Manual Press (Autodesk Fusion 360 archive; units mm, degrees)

design "Manual Press" references "Handle", "Gear", "Rod", "Press Top", "Shaft", "Rack", "Base Plate", "Cover Plate", "Shaft Cap"
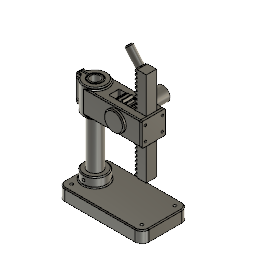
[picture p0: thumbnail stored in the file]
component_insert "Component Insert1"
ground "Ground1"
component_insert "Component Insert2"
joint "Assemble1" OffsetX 0 OffsetY 0 OffsetZ 0 AngleZ 0 OffsetX 0 OffsetY 0 OffsetZ 0 AngleZ 0 alignAngle 0 alignOffsetX 0 alignOffsetY 0 alignOffsetZ 0
component_insert "Component Insert4"
joint "Assemble2" OffsetX 0 OffsetY 0 OffsetZ 0 AngleZ 0 OffsetX 0 OffsetY 0 OffsetZ 0 AngleZ 0 alignAngle 0 alignOffsetX 0 alignOffsetY 0 alignOffsetZ 0
component_insert "Component Insert5"
joint "Assemble3" OffsetX 0 OffsetY 0 OffsetZ 0 AngleZ 0 OffsetX 0 OffsetY 0 OffsetZ 0 AngleZ 0 alignAngle 0 alignOffsetX 0 alignOffsetY 0 alignOffsetZ 0
component_insert "Component Insert6"
joint "Assemble4" OffsetX 0 OffsetY 0 OffsetZ 0 AngleZ 0 OffsetX 0 OffsetY 0 OffsetZ 0 AngleZ 0 alignAngle 0 alignOffsetX 0 alignOffsetY 0 alignOffsetZ 0
component_insert "Component Insert7"
joint "Assemble5" OffsetX 0 OffsetY 0 OffsetZ 0 AngleZ 0 OffsetX 0 OffsetY 0 OffsetZ 0 AngleZ 0 alignAngle 0 alignOffsetX 0 alignOffsetY 0 alignOffsetZ 0
component_insert "Component Insert8"
joint "Assemble6" OffsetX 0 OffsetY 0 OffsetZ 0 AngleZ 0 OffsetX 0 OffsetY 0 OffsetZ 0 AngleZ 0 alignAngle 0 alignOffsetX 0 alignOffsetY 0 alignOffsetZ 0 DistanceMinimum -55 DistanceMaximum 60
component_insert "Component Insert9"
position "Position1"
joint "Assemble7" OffsetX 0 OffsetY 0 OffsetZ 0 AngleZ 0 OffsetX 0 OffsetY 0 OffsetZ 0 AngleZ 0 alignAngle 0 alignOffsetX 0 alignOffsetY 0 alignOffsetZ 0
component_insert "Component Insert10"
joint "Assemble8" OffsetX 0 OffsetY 0 OffsetZ 0 AngleZ 0 OffsetX 0 OffsetY 0 OffsetZ 0 AngleZ 0 alignAngle 0 alignOffsetX 0 alignOffsetY 0 alignOffsetZ 0
position "Position2"
motion_link "MotionLink1" Value1 360 Value2 160

design "Base Plate"
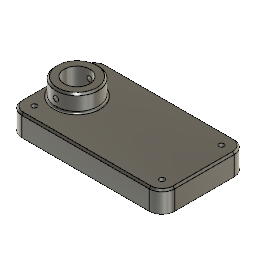
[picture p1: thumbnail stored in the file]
sketch "Sketch1" plane through (0, 0, 0) normal (0, 0, 1) x axis (1, 0, 0)
  line L1 (-90, 50) -> (90, 50)
  line L2 (-90, -50) -> (-90, 50)
  line L3 (90, -50) -> (-90, -50)
  line L4 (90, 50) -> (90, -50)
  line L5 (-90, -50) -> (90, 50)
  line L6 (90, -50) -> (-90, 50)
  point P6 (0, 0)
  point P1 (0, 0)
  point P4 (-90, -50)
  point P5 (90, -50)
  point P3 (-90, 50)
  horizontal L1
  perpendicular L1 L2
  parallel L1 L3
  parallel L2 L4
  coincident L5 P6
  coincident L6 P6
  coincident P1 P6
  dimension "d1" distance P4 P5 = 180
  dimension "d2" distance P3 P4 = 100
extrude "Extrude1" new body sketch "Sketch1" profile of L1 L2 L3 L4 along normal blind 25
fillet "Fillet1" radius 15
sketch "Sketch2" plane through (0, 0, 25) normal (0, 0, 1) x axis (-1, 0, 0)
  line L1 (90, 35) -> (90, -35)
  line L2 (-75, 50) -> (75, 50)
  line L3 (-90, -35) -> (-90, 35)
  line L4 (75, -50) -> (-75, -50)
  arc A1 centre (75, -35) radius 15 clockwise from (90, -35) to (75, -50)
  arc A2 centre (75, 35) radius 15 clockwise from (75, 50) to (90, 35)
  arc A3 centre (-75, 35) radius 15 clockwise from (-90, 35) to (-75, 50)
  arc A4 centre (-75, -35) radius 15 clockwise from (-75, -50) to (-90, -35)
  circle C1 centre (60, 0) radius 15
  point P14 (60, 0)
  dimension "d6" distance L1 P14 = 30
  dimension "d7" distance L4 P14 = 50
  dimension "d8" diameter C1 = 30
extrude "Extrude2" cut sketch "Sketch2" profile of C1 no distance stored
sketch "Sketch3" plane through (0, 0, 25) normal (0, 0, 1) x axis (-1, 0, 0)
  line L1 (90, 35) -> (90, -35)
  line L2 (-75, 50) -> (75, 50)
  line L3 (-90, -35) -> (-90, 35)
  line L4 (75, -50) -> (-75, -50)
  circle C1 centre (60, 0) radius 15
  arc A1 centre (75, -35) radius 15 clockwise from (90, -35) to (75, -50)
  arc A2 centre (75, 35) radius 15 clockwise from (75, 50) to (90, 35)
  arc A3 centre (-75, 35) radius 15 clockwise from (-90, 35) to (-75, 50)
  arc A4 centre (-75, -35) radius 15 clockwise from (-75, -50) to (-90, -35)
  circle C2 centre (60, 0) radius 15
  circle C3 centre (60, 0) radius 25
  concentric C1 C2
  concentric C1 C3
  equal C1 C2
  dimension "d10" diameter C3 = 50
extrude "Extrude3" add sketch "Sketch3" profile of C1 C2 C3 along normal blind 20
chamfer "Chamfer1" distance 2 rotateAngle 45
fillet "Fillet2" radius 2
sketch "Sketch4" plane through (0, 0, 0) normal (0, 1, 0) x axis (1, 0, 0)
  line L1 (-35, -45) -> (-85, -45)
  line L2 (75, 0) -> (-75, 0)
  circle C1 centre (-60, -35) radius 3
  point P2 (-60, -35)
  point P3 (-85, -45)
  dimension "d16" diameter C1 = 6
  dimension "d18" distance P2 P3 = 25
  dimension "d28" distance P2 L2 = 35
extrude "Extrude4" cut sketch "Sketch4" profile of C1 no distance stored
chamfer "Chamfer2" distance 2 rotateAngle 45
sketch "Sketch5" plane through (0, 0, 25) normal (0, 0, 1) x axis (-1, 0, 0)
  line L1 (75, -48) -> (-75, -48)
  line L2 (88, 35) -> (88, -35)
  line L3 (-75, 48) -> (75, 48)
  line L4 (-88, -35) -> (-88, 35)
  arc A1 centre (-75, -35) radius 13 clockwise from (-75, -48) to (-88, -35)
  arc A2 centre (75, -35) radius 13 clockwise from (88, -35) to (75, -48)
  arc A3 centre (75, 35) radius 13 clockwise from (75, 48) to (88, 35)
  arc A4 centre (-75, 35) radius 13 clockwise from (-88, 35) to (-75, 48)
  circle C1 centre (60, 0) radius 27
  circle C2 centre (75, 35) radius 3
  concentric A3 C2
  dimension "d22" diameter C2 = 6
extrude "Extrude5" cut sketch "Sketch5" profile of C2 no distance stored
rectangular_pattern "R-Pattern1" uSpaceDistance 150 vSpaceDistance 70

design "Shaft Cap"
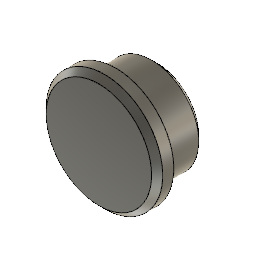
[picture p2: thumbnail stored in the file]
sketch "Sketch1" plane through (0, 0, 0) normal (0, 1, 0) x axis (1, 0, 0)
  circle C1 centre (0, 0) radius 17
  circle C2 centre (0, 0) radius 10
  point P1 (0, 0)
  point P2 (0, 0)
  point P3 (0, 0)
  coincident P1 P2
  coincident P1 P3
  dimension "d1" diameter C1 = 34
  dimension "d5" diameter C2 = 20
extrude "Extrude1" new body sketch "Sketch1" along normal blind 15
sketch "Sketch3" plane through (0, 0, 0) normal (0, -1, 0) x axis (1, 0, 0)
  circle C1 centre (0, 0) radius 10
  circle C2 centre (0, 0) radius 17
  circle C3 centre (0, 0) radius 21
  point P1 (0, 0)
  point P3 (0, 0)
  coincident P1 P3
  dimension "d6" diameter C3 = 42
extrude "Extrude2" add sketch "Sketch3" along normal blind 6
chamfer "Chamfer1" distance 2 rotateAngle 45
chamfer "Chamfer2" distance 2 rotateAngle 45

design "Rack"
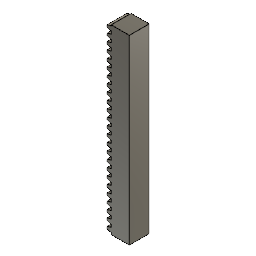
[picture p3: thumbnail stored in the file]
sketch "Sketch1" plane through (0, 0, 0) normal (0, 1, 0) x axis (1, 0, 0)
  line L1 (-10, -100) -> (10, -100)
  line L2 (-10, 100) -> (-10, -100)
  line L3 (10, 100) -> (-10, 100)
  line L4 (10, -100) -> (10, 100)
  line L5 (-10, 100) -> (10, -100)
  line L6 (10, 100) -> (-10, -100)
  point P6 (0, 0)
  point P1 (0, 0)
  point P2 (10, -100)
  point P3 (-10, -100)
  point P5 (10, 100)
  horizontal L1
  perpendicular L1 L2
  parallel L1 L3
  parallel L2 L4
  coincident L5 P6
  coincident L6 P6
  coincident P1 P6
  dimension "d1" distance P2 P3 = 20
  dimension "d2" distance P2 P5 = 200
extrude "Extrude1" new body sketch "Sketch1" profile of L1 L2 L3 L4 distance 22
sketch "Sketch2" plane through (0, -11, 0) normal (0, -1, 0) x axis (1, 0, 0)
  line L1 (10, -100) -> (-10, -100)
  line L2 (10, 100) -> (10, -100)
  line L3 (-10, 100) -> (10, 100)
  line L4 (-10, -100) -> (-10, 100)
  line L5 (-15, -96.5) -> (-15, -94.5)
  line L6 (-7.2745, -95.5) -> (-15, -95.5)
  arc A1 centre (-8.2555, -83.1018) radius 15 clockwise from (-10, -98) to (-15, -96.5)
  arc A2 centre (-8.2555, -107.8982) radius 15 clockwise from (-15, -94.5) to (-10, -93)
  point P8 (-10, -98)
  point P10 (-10, -93)
  point P12 (-15, -95.5)
  point P6 (-15, -94.5)
  point P7 (-15, -96.5)
  parallel L4 L5
  coincident L4 P8
  coincident L4 P10
  equal A1 A2
  midpoint L5 P12
  perpendicular L5 L6
  symmetric P8 P10 L6
  dimension "d5" distance L4 L5 = 5
  dimension "d6" distance P6 P7 = 2
  dimension "d7" radius A2 = 15
  dimension "d8" distance L1 P8 = 2
  dimension "d9" distance P8 P10 = 5
extrude "Extrude2" add sketch "Sketch2" profile of L4 L5 A1 A2 to an object
rectangular_pattern "R-Pattern1" countU 25 uSpaceDistance -8 vSpaceDistance 0

design "Handle"
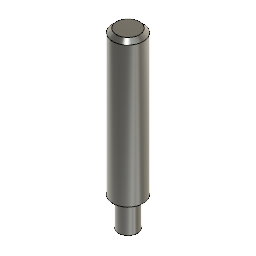
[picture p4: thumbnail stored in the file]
sketch "Sketch1" plane through (0, 0, 0) normal (0, 0, 1) x axis (1, 0, 0)
  circle C1 centre (0, 0) radius 8
  point P1 (0, 0)
  point P2 (0, 0)
  coincident P1 P2
  dimension "d1" diameter C1 = 16
extrude "Extrude1" new body sketch "Sketch1" along normal blind 75
sketch "Sketch2" plane through (0, 0, 0) normal (0, 0, -1) x axis (1, 0, 0)
  circle C1 centre (0, 0) radius 8
  circle C2 centre (0, 0) radius 5
  point P1 (0, 0)
  point P3 (0, 0)
  coincident P1 P3
  dimension "d4" diameter C2 = 10
extrude "Extrude2" add sketch "Sketch2" profile of C2 along normal blind 15
chamfer "Chamfer1" distance 2 rotateAngle 45

design "Cover Plate"
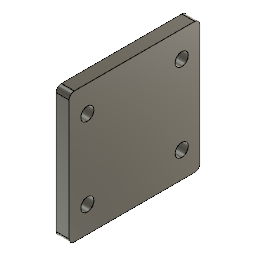
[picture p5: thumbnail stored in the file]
sketch "Sketch1" plane through (0, 0, 0) normal (1, 0, 0) x axis (0, 1, 0)
  line L1 (-25, 25) -> (25, 25)
  line L2 (-25, -25) -> (-25, 25)
  line L3 (25, -25) -> (-25, -25)
  line L4 (25, 25) -> (25, -25)
  line L5 (-25, -25) -> (25, 25)
  line L6 (25, -25) -> (-25, 25)
  point P6 (0, 0)
  point P1 (0, 0)
  point P3 (-25, 25)
  point P4 (-25, -25)
  point P5 (25, -25)
  horizontal L1
  perpendicular L1 L2
  parallel L1 L3
  parallel L2 L4
  coincident L5 P6
  coincident L6 P6
  coincident P1 P6
  dimension "d1" distance P3 P4 = 50
  dimension "d2" distance P4 P5 = 50
extrude "Extrude1" new body sketch "Sketch1" profile of L1 L2 L3 L4 along normal blind 5
fillet "Fillet1" radius 2
hole "Hole1" HoleDepth 5 HoleDiameter 5 TipAngle 118 RefDim1 10 RefDim2 7
rectangular_pattern "R-Pattern1" uSpaceDistance 36 vSpaceDistance 30

design "Shaft"
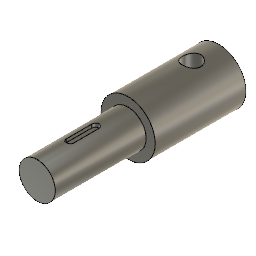
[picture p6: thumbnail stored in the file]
sketch "Sketch1" plane through (0, 0, 0) normal (0, 1, 0) x axis (1, 0, 0)
  circle C1 centre (0, 0) radius 10
  point P1 (0, 0)
  point P2 (0, 0)
  coincident P1 P2
  dimension "d1" diameter C1 = 20
  dimension "d21" distance = 15
extrude "Extrude1" new body sketch "Sketch1" along normal blind 50
sketch "Sketch2" plane through (0, 50, 0) normal (0, 1, 0) x axis (-1, 0, 0)
  circle C1 centre (0, 0) radius 10
  circle C2 centre (0, 0) radius 15
  point P1 (0, 0)
  point P3 (0, 0)
  coincident P1 P3
  dimension "d4" diameter C2 = 30
extrude "Extrude2" add sketch "Sketch2" along normal blind 50
work_plane "WorkPlane1" AlongDistance 10
sketch "Sketch3" plane through (0, 0, 10) normal (0, 0, 1) x axis (1, 0, 0)
  line L1 (2, 32) -> (2, 18)
  line L2 (-2, 18) -> (-2, 32)
  line L3 (0, 32) -> (0, 18)
  line L4 (-15, 50) -> (15, 50)
  arc A1 centre (0, 32) radius 2 clockwise from (-2, 32) to (2, 32)
  arc A2 centre (0, 18) radius 2 clockwise from (2, 18) to (-2, 18)
  point P8 (0, 25)
  point P1 (0, 0)
  point P6 (0, 18)
  point P7 (0, 32)
  tangent L1 A1
  tangent A1 L2
  parallel L1 L2
  tangent L2 A2
  tangent L1 A2
  vertical L3
  midpoint L3 P8
  vertical P1 P6
  dimension "d12" radius A2 = 2
  dimension "d13" distance P6 P7 = 14
  dimension "d14" distance P8 L4 = 25
extrude "Extrude3" cut sketch "Sketch3" profile of L1 A1 L2 A2 against normal blind 2
work_plane "WorkPlane2" AlongDistance 15
sketch "Sketch4" plane through (0, 0, 15) normal (0, 0, 1) x axis (1, 0, 0)
  line L1 (-15, 100) -> (15, 100)
  circle C1 centre (0, 85) radius 5
  point P1 (0, 0)
  point P2 (0, 85)
  vertical P1 P2
  dimension "d20" diameter C1 = 10
  dimension "d24" distance P2 L1 = 15
extrude "Extrude4" cut sketch "Sketch4" profile of C1 against normal blind 15

design "Gear"
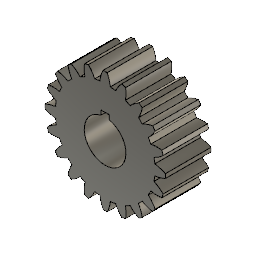
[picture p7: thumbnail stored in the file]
sketch "Sketch1" plane through (0, 0, 0) normal (0, 1, 0) x axis (1, 0, 0)
  circle C1 centre (0, 0) radius 24
  circle C2 centre (0, 0) radius 10
  point P1 (0, 0)
  point P2 (0, 0)
  coincident P1 P2
  concentric C1 C2
  dimension "d1" diameter C1 = 48
  dimension "d2" diameter C2 = 20
extrude "Extrude1" new body sketch "Sketch1" distance 22
sketch "Sketch2" plane through (0, -11, 0) normal (0, -1, 0) x axis (1, 0, 0)
  line L1 (0, 34.5824) -> (0, 0)
  line L2 (1, 29) -> (-1, 29)
  circle C1 centre (0, 0) radius 10
  circle C2 centre (0, 0) radius 24
  arc A1 centre (12.4169, 22.2928) radius 15 clockwise from (-2.5, 23.8694) to (-1, 29)
  arc A2 centre (-12.4169, 22.2928) radius 15 clockwise from (1, 29) to (2.5, 23.8694)
  point P1 (0, 0)
  point P3 (0, 0)
  point P5 (-1, 29)
  point P6 (1, 29)
  point P7 (-2.5, 23.8694)
  point P9 (2.5, 23.8694)
  coincident P1 P3
  vertical L1
  perpendicular L1 L2
  symmetric L1 P5 P6
  coincident C2 P7
  coincident C2 P9
  equal A1 A2
  symmetric L1 P7 P9
  dimension "d5" distance P5 P6 = 2
  dimension "d6" distance P1 L2 = 29
  dimension "d7" radius A1 = 15
  dimension "d8" distance P7 P9 = 5
extrude "Extrude2" add sketch "Sketch2" + "Sketch1" profile of S1:C2 S1:L2 S1:A1 S1:A2 to an object
circular_pattern "C-Pattern1" countU 20 TotalAngle 360
sketch "Sketch3" plane through (0, -11, 0) normal (0, -1, 0) x axis (1, 0, 0)
  line L1 (-9.9125, 27.2716) -> (-8.0104, 27.8897)
  line L2 (-17.8548, 22.8737) -> (-16.2368, 24.0493)
  line L3 (-24.0493, 16.2368) -> (-22.8737, 17.8548)
  line L4 (-27.8897, 8.0104) -> (-27.2716, 9.9125)
  line L5 (-29, -1) -> (-29, 1)
  line L6 (-27.2716, -9.9125) -> (-27.8897, -8.0104)
  line L7 (-22.8737, -17.8548) -> (-24.0493, -16.2368)
  line L8 (-16.2368, -24.0493) -> (-17.8548, -22.8737)
  line L9 (-8.0104, -27.8897) -> (-9.9125, -27.2716)
  line L10 (1, -29) -> (-1, -29)
  line L11 (9.9125, -27.2716) -> (8.0104, -27.8897)
  line L12 (17.8548, -22.8737) -> (16.2368, -24.0493)
  line L13 (24.0493, -16.2368) -> (22.8737, -17.8548)
  line L14 (27.8897, -8.0104) -> (27.2716, -9.9125)
  line L15 (29, 1) -> (29, -1)
  line L16 (27.2716, 9.9125) -> (27.8897, 8.0104)
  line L17 (22.8737, 17.8548) -> (24.0493, 16.2368)
  line L18 (16.2368, 24.0493) -> (17.8548, 22.8737)
  line L19 (8.0104, 27.8897) -> (9.9125, 27.2716)
  line L20 (-1, 29) -> (1, 29)
  line L21 (2, 12) -> (-2, 12)
  line L22 (2, 9.798) -> (2, 12)
  line L23 (-2, 12) -> (-2, 9.798)
  line L24 (0, 15.9163) -> (0, 0)
  circle C1 centre (0, 0) radius 10
  arc A1 centre (0, 0) radius 24 clockwise from (-4.9984, 23.4737) to (-2.5, 23.8694)
  arc A2 centre (-18.698, 17.3647) radius 15 clockwise from (-8.0104, 27.8897) to (-4.9984, 23.4737)
  arc A3 centre (4.9203, 25.0388) radius 15 clockwise from (-9.7537, 21.9286) to (-9.9125, 27.2716)
  arc A4 centre (0, 0) radius 24 clockwise from (-12.0076, 20.7802) to (-9.7537, 21.9286)
  arc A5 centre (-23.1489, 10.7368) radius 15 clockwise from (-16.2368, 24.0493) to (-12.0076, 20.7802)
  arc A6 centre (-3.0579, 25.3337) radius 15 clockwise from (-16.0526, 17.8413) to (-17.8548, 22.8737)
  arc A7 centre (0, 0) radius 24 clockwise from (-17.8413, 16.0526) to (-16.0526, 17.8413)
  arc A8 centre (-25.3337, 3.0579) radius 15 clockwise from (-22.8737, 17.8548) to (-17.8413, 16.0526)
  arc A9 centre (-10.7368, 23.1489) radius 15 clockwise from (-20.7802, 12.0076) to (-24.0493, 16.2368)
  arc A10 centre (0, 0) radius 24 clockwise from (-21.9286, 9.7537) to (-20.7802, 12.0076)
  arc A11 centre (-25.0388, -4.9203) radius 15 clockwise from (-27.2716, 9.9125) to (-21.9286, 9.7537)
  arc A12 centre (-17.3647, 18.698) radius 15 clockwise from (-23.4737, 4.9984) to (-27.8897, 8.0104)
  arc A13 centre (0, 0) radius 24 clockwise from (-23.8694, 2.5) to (-23.4737, 4.9984)
  arc A14 centre (-22.2928, -12.4169) radius 15 clockwise from (-29, 1) to (-23.8694, 2.5)
  arc A15 centre (-22.2928, 12.4169) radius 15 clockwise from (-23.8694, -2.5) to (-29, -1)
  arc A16 centre (0, 0) radius 24 clockwise from (-23.4737, -4.9984) to (-23.8694, -2.5)
  arc A17 centre (-17.3647, -18.698) radius 15 clockwise from (-27.8897, -8.0104) to (-23.4737, -4.9984)
  arc A18 centre (-25.0388, 4.9203) radius 15 clockwise from (-21.9286, -9.7537) to (-27.2716, -9.9125)
  arc A19 centre (0, 0) radius 24 clockwise from (-20.7802, -12.0076) to (-21.9286, -9.7537)
  arc A20 centre (-10.7368, -23.1489) radius 15 clockwise from (-24.0493, -16.2368) to (-20.7802, -12.0076)
  arc A21 centre (-25.3337, -3.0579) radius 15 clockwise from (-17.8413, -16.0526) to (-22.8737, -17.8548)
  arc A22 centre (0, 0) radius 24 clockwise from (-16.0526, -17.8413) to (-17.8413, -16.0526)
  arc A23 centre (-3.0579, -25.3337) radius 15 clockwise from (-17.8548, -22.8737) to (-16.0526, -17.8413)
  arc A24 centre (-23.1489, -10.7368) radius 15 clockwise from (-12.0076, -20.7802) to (-16.2368, -24.0493)
  arc A25 centre (0, 0) radius 24 clockwise from (-9.7537, -21.9286) to (-12.0076, -20.7802)
  arc A26 centre (4.9203, -25.0388) radius 15 clockwise from (-9.9125, -27.2716) to (-9.7537, -21.9286)
  arc A27 centre (-18.698, -17.3647) radius 15 clockwise from (-4.9984, -23.4737) to (-8.0104, -27.8897)
  arc A28 centre (0, 0) radius 24 clockwise from (-2.5, -23.8694) to (-4.9984, -23.4737)
  arc A29 centre (12.4169, -22.2928) radius 15 clockwise from (-1, -29) to (-2.5, -23.8694)
  arc A30 centre (-12.4169, -22.2928) radius 15 clockwise from (2.5, -23.8694) to (1, -29)
  arc A31 centre (0, 0) radius 24 clockwise from (4.9984, -23.4737) to (2.5, -23.8694)
  arc A32 centre (18.698, -17.3647) radius 15 clockwise from (8.0104, -27.8897) to (4.9984, -23.4737)
  arc A33 centre (-4.9203, -25.0388) radius 15 clockwise from (9.7537, -21.9286) to (9.9125, -27.2716)
  arc A34 centre (0, 0) radius 24 clockwise from (12.0076, -20.7802) to (9.7537, -21.9286)
  arc A35 centre (23.1489, -10.7368) radius 15 clockwise from (16.2368, -24.0493) to (12.0076, -20.7802)
  arc A36 centre (3.0579, -25.3337) radius 15 clockwise from (16.0526, -17.8413) to (17.8548, -22.8737)
  arc A37 centre (0, 0) radius 24 clockwise from (17.8413, -16.0526) to (16.0526, -17.8413)
  arc A38 centre (25.3337, -3.0579) radius 15 clockwise from (22.8737, -17.8548) to (17.8413, -16.0526)
  arc A39 centre (10.7368, -23.1489) radius 15 clockwise from (20.7802, -12.0076) to (24.0493, -16.2368)
  arc A40 centre (0, 0) radius 24 clockwise from (21.9286, -9.7537) to (20.7802, -12.0076)
  arc A41 centre (25.0388, 4.9203) radius 15 clockwise from (27.2716, -9.9125) to (21.9286, -9.7537)
  arc A42 centre (17.3647, -18.698) radius 15 clockwise from (23.4737, -4.9984) to (27.8897, -8.0104)
  arc A43 centre (0, 0) radius 24 clockwise from (23.8694, -2.5) to (23.4737, -4.9984)
  arc A44 centre (22.2928, 12.4169) radius 15 clockwise from (29, -1) to (23.8694, -2.5)
  arc A45 centre (22.2928, -12.4169) radius 15 clockwise from (23.8694, 2.5) to (29, 1)
  arc A46 centre (0, 0) radius 24 clockwise from (23.4737, 4.9984) to (23.8694, 2.5)
  arc A47 centre (17.3647, 18.698) radius 15 clockwise from (27.8897, 8.0104) to (23.4737, 4.9984)
  arc A48 centre (25.0388, -4.9203) radius 15 clockwise from (21.9286, 9.7537) to (27.2716, 9.9125)
  arc A49 centre (0, 0) radius 24 clockwise from (20.7802, 12.0076) to (21.9286, 9.7537)
  arc A50 centre (10.7368, 23.1489) radius 15 clockwise from (24.0493, 16.2368) to (20.7802, 12.0076)
  arc A51 centre (25.3337, 3.0579) radius 15 clockwise from (17.8413, 16.0526) to (22.8737, 17.8548)
  arc A52 centre (0, 0) radius 24 clockwise from (16.0526, 17.8413) to (17.8413, 16.0526)
  arc A53 centre (3.0579, 25.3337) radius 15 clockwise from (17.8548, 22.8737) to (16.0526, 17.8413)
  arc A54 centre (23.1489, 10.7368) radius 15 clockwise from (12.0076, 20.7802) to (16.2368, 24.0493)
  arc A55 centre (0, 0) radius 24 clockwise from (9.7537, 21.9286) to (12.0076, 20.7802)
  arc A56 centre (-4.9203, 25.0388) radius 15 clockwise from (9.9125, 27.2716) to (9.7537, 21.9286)
  arc A57 centre (18.698, 17.3647) radius 15 clockwise from (4.9984, 23.4737) to (8.0104, 27.8897)
  arc A58 centre (0, 0) radius 24 clockwise from (2.5, 23.8694) to (4.9984, 23.4737)
  arc A59 centre (-12.4169, 22.2928) radius 15 clockwise from (1, 29) to (2.5, 23.8694)
  arc A60 centre (12.4169, 22.2928) radius 15 clockwise from (-2.5, 23.8694) to (-1, 29)
  point P2 (0, 0)
  point P125 (0, 0)
  point P127 (-2, 9.798)
  point P128 (2, 9.798)
  point P123 (-2, 12)
  point P124 (2, 12)
  horizontal L21
  vertical L22
  vertical L23
  coincident P2 P125
  vertical L24
  symmetric L22 L23 L24
  coincident C1 P127
  coincident C1 P128
  dimension "d13" distance P123 P124 = 4
  dimension "d14" distance L21 P125 = 12
extrude "Extrude3" cut sketch "Sketch3" + "Sketch1" profile of S1:C1 S1:L21 S1:L22 S1:L23 to an object

design "Press Top"
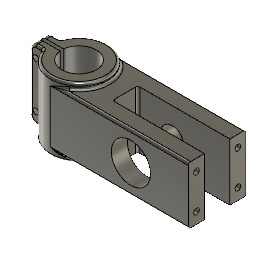
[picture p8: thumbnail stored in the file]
sketch "Sketch1" plane through (0, 0, 0) normal (0, 0, 1) x axis (1, 0, 0)
  circle C1 centre (0, 0) radius 25
  circle C2 centre (0, 0) radius 15
  point P1 (0, 0)
  point P2 (0, 0)
  point P3 (0, 0)
  coincident P1 P2
  coincident P1 P3
  dimension "d1" diameter C1 = 50
  dimension "d2" diameter C2 = 30
extrude "Extrude1" new body sketch "Sketch1" + "Sketch5" profile of S1:C1 S1:C2 distance 60
sketch "Sketch2" plane through (0, 0, 0) normal (0, 0, 1) x axis (1, 0, 0)
  line L1 (120, 25) -> (0, 25)
  line L2 (120, 11) -> (120, 25)
  line L3 (40, 11) -> (120, 11)
  line L4 (40, -11) -> (40, 11)
  line L5 (120, -11) -> (40, -11)
  line L6 (120, -25) -> (120, -11)
  line L7 (0, -25) -> (120, -25)
  circle C1 centre (0, 0) radius 25
  circle C2 centre (0, 0) radius 25
  point P4 (0, 25)
  point P11 (0, -25)
  point P1 (0, 0)
  point P5 (120, 25)
  point P6 (120, 11)
  point P8 (40, -11)
  point P9 (120, -11)
  coincident C1 P4
  coincident C2 P4
  horizontal L1
  perpendicular L1 L2
  perpendicular L2 L3
  perpendicular L3 L4
  perpendicular L4 L5
  perpendicular L5 L6
  coincident C2 P11
  tangent C2 L1
  tangent C1 L7
  horizontal L7
  equal L1 L7
  equal L2 L6
  dimension "d5" distance P1 L2 = 120
  dimension "d6" distance P5 P6 = 14
  dimension "d7" distance P8 P9 = 80
extrude "Extrude2" add sketch "Sketch2" distance 50
sketch "Sketch3" plane through (0, -25, 0) normal (0, -1, 0) x axis (1, 0, 0)
  line L1 (120, 25) -> (120, -25)
  line L2 (0, 25) -> (120, 25)
  line L3 (0, -25) -> (0, 25)
  line L4 (120, -25) -> (0, -25)
  circle C1 centre (70, 0) radius 10
  point P1 (0, 0)
  point P6 (70, 0)
  horizontal P1 P6
  dimension "d10" diameter C1 = 20
  dimension "d11" distance L1 P6 = 50
extrude "Extrude3" cut sketch "Sketch3" profile of C1 no distance stored
sketch "Sketch4" plane through (0, -25, 0) normal (0, -1, 0) x axis (1, 0, 0)
  line L1 (120, 25) -> (120, -25)
  line L2 (0, 25) -> (120, 25)
  line L3 (0, -25) -> (0, 25)
  line L4 (120, -25) -> (0, -25)
  circle C1 centre (70, 0) radius 10
  circle C2 centre (70, 0) radius 17
  concentric C1 C2
  dimension "d13" diameter C2 = 34
extrude "Extrude4" cut sketch "Sketch4" profile of C1 C2 to an object
sketch "Sketch5" plane through (0, 0, 30) normal (0, 0, 1) x axis (-1, 0, 0)
  line L1 (39.7862, 0) -> (0, 0)
  line L2 (23.8485, -7.5) -> (35, -7.5)
  line L3 (35, 7.5) -> (23.8485, 7.5)
  line L4 (35, -7.5) -> (35, 7.5)
  circle C1 centre (0, 0) radius 15
  circle C2 centre (0, 0) radius 25
  point P1 (0, 0)
  point P3 (0, 0)
  point P7 (23.8485, -7.5)
  point P8 (23.8485, 7.5)
  point P5 (35, -7.5)
  point P6 (35, 7.5)
  coincident P1 P3
  horizontal L1
  horizontal L2
  horizontal L3
  vertical L4
  coincident C2 P7
  coincident C2 P8
  symmetric L1 L2 L3
  dimension "d16" distance P5 P6 = 15
  dimension "d17" distance P1 L4 = 35
extrude "Extrude5" add sketch "Sketch5" profile of C2 L2 L3 L4 to an object
sketch "Sketch6" plane through (0, 0, 30) normal (0, 0, 1) x axis (-1, 0, 0)
  line L1 (35, -7.5) -> (23.8485, -7.5)
  line L2 (35, 7.5) -> (35, -7.5)
  line L3 (23.8485, 7.5) -> (35, 7.5)
  line L4 (14.9248, -1.5) -> (35, -1.5)
  line L5 (35, 1.5) -> (14.9248, 1.5)
  line L6 (35, -1.5) -> (35, 1.5)
  line L7 (44.3048, 0) -> (0, 0)
  circle C1 centre (0, 0) radius 15
  arc A1 centre (0, 0) radius 25 clockwise from (23.8485, -7.5) to (23.8485, 7.5)
  arc A2 centre (0, 0) radius 15 clockwise from (14.9248, 1.5) to (14.9248, -1.5)
  point P1 (0, 0)
  point P9 (0, 0)
  point P11 (0, 0)
  point P7 (35, -1.5)
  point P8 (35, 1.5)
  horizontal L4
  horizontal L5
  vertical L6
  coincident P1 P9
  horizontal L7
  symmetric L4 L5 L7
  collinear L2 L6
  coincident P1 P11
  equal C1 A2
  dimension "d20" distance P7 P8 = 3
extrude "Extrude6" cut sketch "Sketch6" profile of C1 L2 L4 L5 L6 A2 to an object
sketch "Sketch7" plane through (0, -7.5, 0) normal (0, -1, 0) x axis (1, 0, 0)
  line L1 (-23.8485, -30) -> (-35, -30)
  line L2 (-23.8485, 30) -> (-23.8485, -30)
  line L3 (-35, 30) -> (-23.8485, 30)
  line L4 (-35, -30) -> (-35, 30)
  line L5 (-14.9248, 30) -> (-14.9248, -30)
  line L6 (-43.3455, 0) -> (0, 0)
  circle C1 centre (-30, 20) radius 2.5
  circle C2 centre (-30, -20) radius 2.5
  point P6 (-30, 20)
  point P7 (-30, -20)
  point P1 (0, 0)
  point P10 (0, 0)
  equal C1 C2
  vertical P6 P7
  coincident P1 P10
  perpendicular L5 L6
  symmetric P6 P7 L6
  dimension "d23" diameter C1 = 5
  dimension "d24" distance L4 P6 = 5
  dimension "d25" distance P6 P7 = 40
extrude "Extrude7" cut sketch "Sketch7" profile of C1 C2 to an object
hole "Hole1" HoleDepth 25 HoleDiameter 5 TipAngle 118 RefDim1 7 RefDim2 10
rectangular_pattern "R-Pattern1" sketch "Sketch5" uSpaceDistance 30 vSpaceDistance -36
fillet "Fillet1" radius 2 2
fillet "Fillet2" radius 5 2
fillet "Fillet3" radius 2
fillet "Fillet4" radius 2

design "Rod"
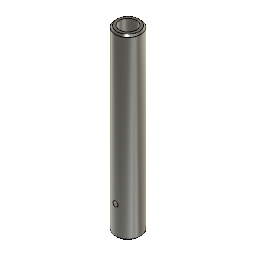
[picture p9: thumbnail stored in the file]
sketch "Sketch1" plane through (0, 0, 0) normal (0, 0, 1) x axis (1, 0, 0)
  circle C1 centre (0, 0) radius 15
  circle C2 centre (0, 0) radius 10
  point P1 (0, 0)
  point P2 (0, 0)
  point P3 (0, 0)
  coincident P1 P2
  coincident P1 P3
  dimension "d1" diameter C1 = 30
  dimension "d2" diameter C2 = 20
extrude "Extrude1" new body sketch "Sketch1" along normal blind 210
chamfer "Chamfer1" distance 2 rotateAngle 45
sketch "Sketch2" plane through (0, 0, 0) normal (0, 1, 0) x axis (1, 0, 0)
  line L1 (13, 0) -> (-13, 0)
  circle C1 centre (0, -35) radius 3
  point P1 (0, 0)
  point P2 (0, -35)
  vertical P1 P2
  dimension "d7" diameter C1 = 6
  dimension "d8" distance P2 L1 = 35
extrude "Extrude2" cut sketch "Sketch2" profile of C1 no distance stored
